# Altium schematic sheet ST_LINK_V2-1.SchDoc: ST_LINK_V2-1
size A3; Date: Not used; ApprovedBy: Not used; CheckedBy: Not used; Author: Not used; CompanyName: STMicroelectronics; DrawnBy: Not used; Engineer: Not used; Organization: Not used; Address1: Not used; Address2: Not used; Address3: Not used; Address4: Not used; DocumentNumber: 8; Revision: Not used; SheetNumber: 8; SheetTotal: 9
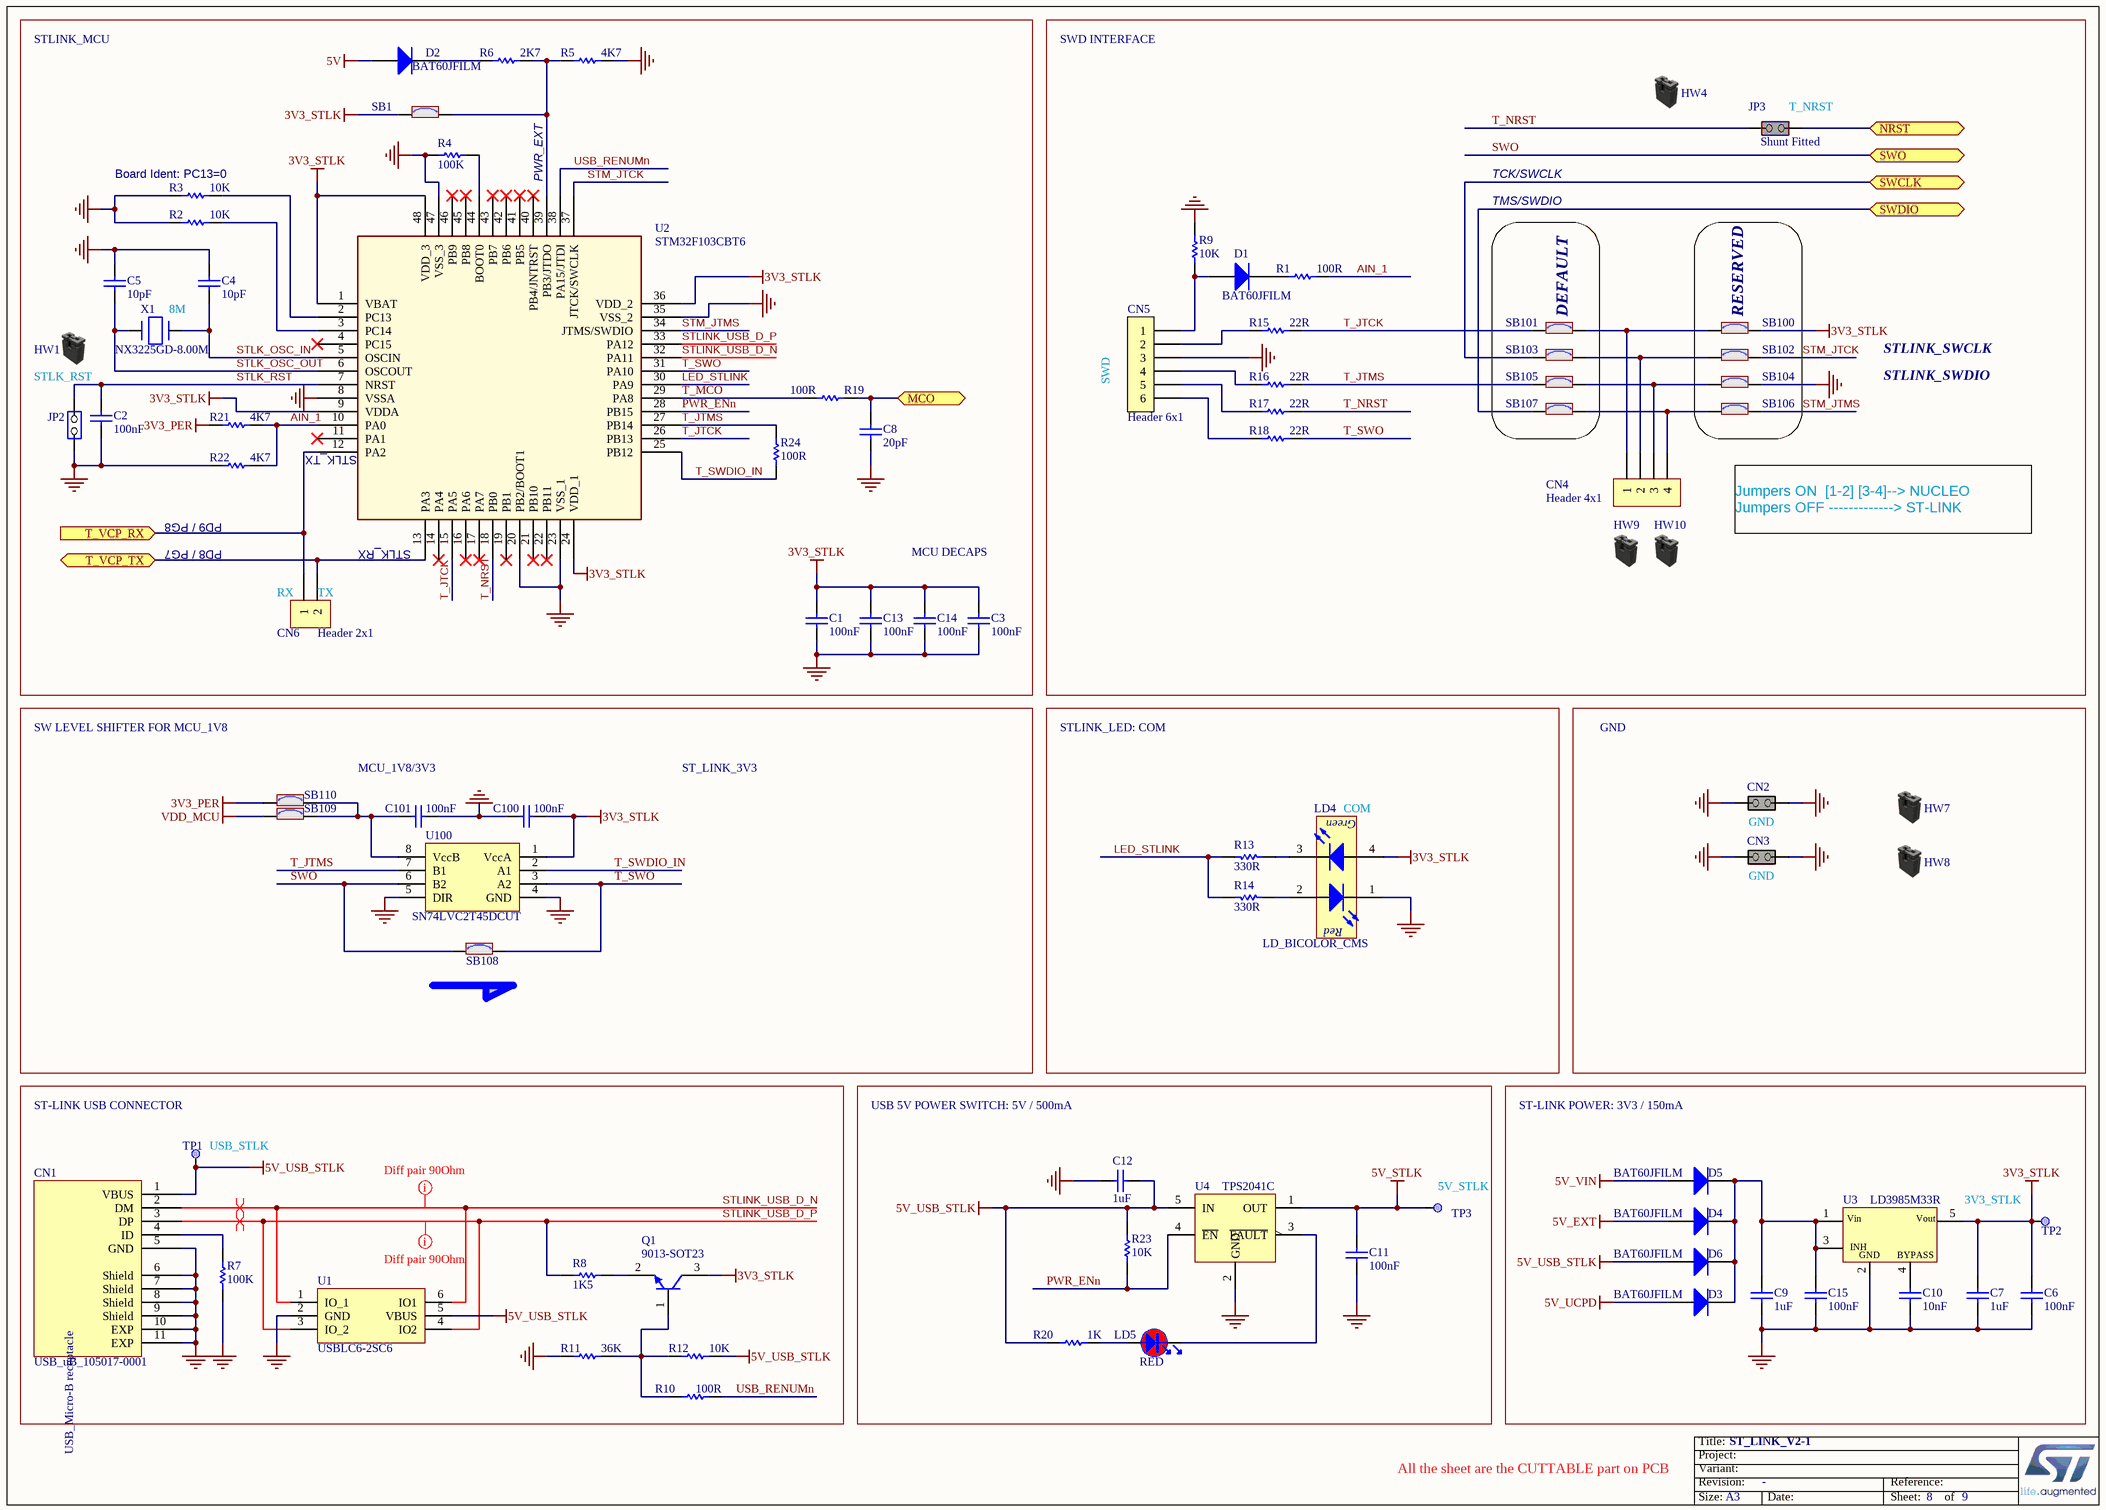
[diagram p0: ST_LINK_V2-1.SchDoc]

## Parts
C1  value 100nF  [C0603]
C2  value 100nF  [C0603]
C3  value 100nF  [C0603]
C4  value 10pF  [C0402]
C5  value 10pF  [C0402]
C6  value 100nF  [C0603]
C7  value 1uF  [C0603]  (hidden comment: Capacitor)
C8  value 20pF  [C0603]
C9  value 1uF  [C0603]
C10  value 10nF  [C0603]
C11  value 100nF  [C0603]
C12  value 1uF  [C0603]  (hidden comment: Capacitor)
C13  value 100nF  [C0603]
C14  value 100nF  [C0603]
C15  value 100nF  [C0603]
C100  value 100nF  [C0603]
C101  value 100nF  [C0603]
CN1  value USB_uB_105017-0001  [CON_USBMICROB_MOLEX_105017-0001_H2P90]
CN2  (no value)  [CON_SAMTEC_TSW-102-09-X-S]
CN3  (no value)  [CON_SAMTEC_TSW-102-09-X-S]
CN4  Header 4x1  [CON_SAMTEC_TSW-104-07-G-S]
CN5  value Header 6x1  [CON_SAMTEC_TSW-106-07-X-S]
CN6  value Header 2x1  [CON_SAMTEC_TSW-102-07-G-S]
D1  value BAT60JFILM  [DIO_SOD323]
D2  value BAT60JFILM  [DIO_SOD323]
D3  value BAT60JFILM  [DIO_SOD323]
D4  value BAT60JFILM  [DIO_SOD323]
D5  value BAT60JFILM  [DIO_SOD323]
D6  value BAT60JFILM  [DIO_SOD323]
HW1  (no value)  (mechanical)
HW4  (no value)  (mechanical)
HW7  (no value)  (mechanical)
HW8  (no value)  (mechanical)
HW9  (no value)  (mechanical)
HW10  (no value)  (mechanical)
JP2  (no value)  [CON_SAMTEC_TSW-102-07-G-S]
JP3  value Shunt Fitted  [CON_SAMTEC_TSW-102-07-G-S]
LD4  value LD_BICOLOR_CMS  [LED_BI-GR_HSMF-A201-A00J1]
LD5  value RED  [LED_0603_RED_H0P4]
Q1  value 9013-SOT23  [NPN_SOT23]
R1  value 100R  [R0603]
R2  value 10K  [R0603]
R3  value 10K  [R0603]
R4  value 100K  [R0603]
R5  value 4K7  [R0603]
R6  value 2K7  [R0603]
R7  value 100K  [R0603]
R8  value 1K5  [R0603]
R9  value 10K  [R0603]
R10  value 100R  [R0603]
R11  value 36K  [R0603]
R12  value 10K  [R0603]
R13  value 330R  [R0603]
R14  value 330R  [R0603]
R15  value 22R  [R0603]
R16  value 22R  [R0603]
R17  value 22R  [R0603]
R18  value 22R  [R0603]
R19  value 100R  [R0603]
R20  value 1K  [R0603]
R21  value 4K7  [R0603]
R22  value 4K7  [R0603]
R23  value 10K  [R0603]
R24  value 100R  [R0603]
SB1  (no value)  [SOLDER-BRIDGE_R0603-0R]
SB100  (no value)  [SOLDER-BRIDGE_R0603-0R]
SB101  (no value)  [SOLDER-BRIDGE_R0603-0R]
SB102  (no value)  [SOLDER-BRIDGE_R0603-0R]
SB103  (no value)  [SOLDER-BRIDGE_R0603-0R]
SB104  (no value)  [SOLDER-BRIDGE_R0603-0R]
SB105  (no value)  [SOLDER-BRIDGE_R0603-0R]
SB106  (no value)  [SOLDER-BRIDGE_R0603-0R]
SB107  (no value)  [SOLDER-BRIDGE_R0603-0R]
SB108  (no value)  [SOLDER-BRIDGE_R0603-0R]
SB109  (no value)  [SOLDER-BRIDGE_R0603-0R]
SB110  (no value)  [SOLDER-BRIDGE_R0603-0R]
TP1  (no value)  [TP_SMD_1MM]  (no BOM)
TP2  (no value)  [TP_SMD_1MM]  (no BOM)
TP3  (no value)  [TP_SMD_1MM]  (no BOM)
U1  value USBLC6-2SC6  [ESD_SOT23-6L]
U2  value STM32F103CBT6  [ICC_LQFP48_7X7_P050]
U3  value LD3985M33R  [REG_SOT23-5L]
U4  TPS2041C  [MOS_SOT23-5L]
U100  value SN74LVC2T45DCUT  [ICC_VSSOP8_DCU_R-PDSO-G8_2X2P30_P050]
X1  value NX3225GD-8.00M  [CRY_NX3225GD_2P]

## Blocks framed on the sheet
DEFAULT: SB101 SB103 SB105 SB107
RESERVED: SB100 SB102 SB104 SB106

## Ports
MCO, NRST, SWCLK, SWDIO, SWO, T_VCP_RX (in), T_VCP_TX

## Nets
3V3_PER: R21.1 SB110.2
3V3_STLK: C1.2 C3.2 C6.2 C7.2 C13.2 C14.2 C100.2 LD4.4(YellowGreen_anode) Q1.3(C) SB1.1 SB100.2 TP2.1 U2.1(VBAT) U2.9(VDDA) U2.24(VDD_1) U2.36(VDD_2) U2.48(VDD_3) U3.5(Vout) U100.1(VccA)
5V: D2.1(A)
5V_EXT: D4.1(A)
5V_STLK: C11.2 TP3.1 U4.1(OUT)
5V_UCPD: D3.1(A)
5V_USB_STLK: C12.2 CN1.1(VBUS) D6.1(A) R12.1 R20.1 R23.1 TP1.1 U1.5(VBUS) U4.5(IN)
5V_VIN: D5.1(A)
GND: C1.1 C2.1 C3.1 C4.2 C5.2 C6.1 C7.1 C8.2 C9.1 C10.1 C11.1 C12.1 C13.1 C14.1 C15.1 C100.1 C101.2 CN1.5(GND) CN1.6(Shield) CN1.7(Shield) CN1.8(Shield) CN1.9(Shield) CN1.10(EXP) CN1.11(EXP) CN2.1(COMMON) CN2.2(NO) CN3.1(COMMON) CN3.2(NO) CN5.3 JP2.1(COMMON) LD4.1(RED_cathode) R2.1 R3.1 R4.1 R5.2 R7.1 R9.2 R11.1 R22.1 SB104.2 U1.2(GND) U2.8(VSSA) U2.20(PB2/BOOT1) U2.23(VSS_1) U2.35(VSS_2) U2.47(VSS_3) U3.2(GND) U4.2(GND) U100.4(GND) U100.5(DIR)
VDD_MCU: SB109.2
AIN_1: R1.2 R21.2 R22.2 U2.10(PA0)
LED_STLINK: R13.2 R14.2 U2.30(PA9)
MCO: C8.1 R19.2 ; port MCO
NRST: JP3.2(NO) ; port NRST
PWR_ENn: R23.2 U2.28(PB15) U4.4(~{EN})
STLINK_USB_D_N: CN1.2(DM) U1.1(IO_1) U1.6(IO1) U2.32(PA11)
STLINK_USB_D_P: CN1.3(DP) R8.2 U1.3(IO_2) U1.4(IO2) U2.33(PA12)
STLK_OSC_IN: C4.1 U2.5(OSCIN) X1.1(X1)
STLK_OSC_OUT: C5.1 U2.6(OSCOUT) X1.2(X2)
STLK_RST: C2.2 JP2.2(NO) U2.7(NRST)
STM_JTCK: SB102.2 U2.37(JTCK/SWCLK)
STM_JTMS: SB106.2 U2.34(JTMS/SWDIO)
SWCLK: SB103.1 ; port SWCLK
SWDIO: SB107.1 ; port SWDIO
SWO: SB108.2 U100.6(B2) ; port SWO
T_JTCK: R15.2 SB101.1 U2.15(PA5) U2.26(PB13)
T_JTMS: R16.2 R24.2 SB105.1 U2.27(PB14) U100.7(B1)
T_MCO: R19.1 U2.29(PA8)
T_NRST: JP3.1(COMMON) R17.2 U2.18(PB0)
T_SWDIO_IN: R24.1 U2.25(PB12) U100.2(A1)
T_SWO: R18.2 SB108.1 U2.31(PA10) U100.3(A2)
T_VCP_RX: CN6.1 U2.12(PA2) ; port T_VCP_RX
T_VCP_TX: CN6.2 U2.13(PA3) ; port T_VCP_TX
USB_RENUMn: R10.2 U2.38(PA15/JTDI)
NetC9_2: C9.2 C15.2 D3.2(K) D4.2(K) D5.2(K) D6.2(K) U3.1(Vin) U3.3(CE)
NetC10_2: C10.2 U3.4(BYPASS)
NetC101_1: C101.1 SB109.1 SB110.1 U100.8(VccB)
NetCN1_4: CN1.4(ID) R7.2
NetCN4_1: CN4.1 SB100.1 SB101.2
NetCN4_2: CN4.2 SB102.1 SB103.2
NetCN4_3: CN4.3 SB104.1 SB105.2
NetCN4_4: CN4.4 SB106.1 SB107.2
NetCN5_1: CN5.1 D1.1(A) R9.1
NetCN5_2: CN5.2 R15.1
NetCN5_4: CN5.4 R16.1
NetCN5_5: CN5.5 R17.1
NetCN5_6: CN5.6 R18.1
NetD1_2: D1.2(K) R1.1
NetD2_2: D2.2(K) R6.1
NetLD4_2: LD4.2(Red_anode) R14.1
NetLD4_3: LD4.3(YellowGreen_cathode) R13.1
NetLD5_1: LD5.1 R20.2
NetLD5_2: LD5.2 U4.3(~{FAULT})
NetQ1_1: Q1.1(B) R10.1 R11.2 R12.2
NetQ1_2: Q1.2(E) R8.1
NetR2_2: R2.2 U2.3(PC14)
NetR3_2: R3.2 U2.2(PC13)
NetR4_2: R4.2 U2.44(BOOT0)
NetR5_1: R5.1 R6.2 SB1.2 U2.39(PB3/JTDO)

Not connected (* = marked no-connect by the designer): U2 4(PC15)* 11(PA1)* 14(PA4)* 16(PA6)* 17(PA7)* 19(PB1)* 21(PB10)* 22(PB11)* 40(PB4/JNTRST)* 41(PB5)* 42(PB6)* 43(PB7)* 45(PB8)* 46(PB9)*

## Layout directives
mark named Diff pair 90Ohm: STLINK_USB_D_N, STLINK_USB_D_P
differential pair: STLINK_USB_D_N, STLINK_USB_D_P

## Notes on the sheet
- STLINK_MCU
- SWD INTERFACE
- (near JP3) T_NRST
- (near R3) Board Ident: PC13=0
- PWR_EXT
- TCK/SWCLK
- TMS/SWDIO
- (near X1) 8M
- STLK_RST
- (near CN5) SWD
- STLINK_SWCLK
- STLINK_SWDIO
- (near U2) STLK_TX
- PD9 / PG8
- PD8 / PG7
- (near U2) STLK_RX
- MCU DECAPS
- Jumpers ON  [1-2] [3-4]--> NUCLEO
  Jumpers OFF -------------> ST-LINK
- (near CN6) RX
- (near CN6) TX
- SW LEVEL SHIFTER FOR MCU_1V8
- MCU_1V8/3V3
- ST_LINK_3V3
- STLINK_LED: COM
- GND
- (near LD4) COM
- (near CN2) GND
- (near CN3) GND
- ST-LINK USB CONNECTOR
- USB 5V POWER SWITCH: 5V / 500mA
- ST-LINK POWER: 3V3 / 150mA
- (near TP1) USB_STLK
- (near TP3) 5V_STLK
- 3V3_STLK
- All the sheet are the CUTTABLE part on PCB

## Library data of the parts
C1-C3 C6 C11 C13-C15 C100 C101 = MCD-00211: Capacitor, MLCC, 100nF, 16V, X7R, 10%, 0603, T=0,8mm; Manufacturer_Part_Number: CC0603KRX7R7BB104; Manufacturer: YAGEO; Provided_By: Subcon; Initial_Board_Reference: MB1319
C4 C5 = MCD-00015: Capacitor, MLCC, 10pF, 50V, NPO, 5%, 0402, T=0,5mm; Manufacturer_Part_Number: CC0402JRNPO9BN100; Manufacturer: YAGEO; Provided_By: subcon; Initial_Board_Reference: MB1274
C7 C12 = MCD-00010: Capacitor, MLCC, 1uF, 16V, X5R, 10%, 0603, T=0,8mm; Manufacturer_Part_Number: CC0603KRX5R7BB105; Manufacturer: YAGEO; Provided_By: SUBCO
C8 = MCD-00638: Capacitor, MLCC, 20pF, 50V, NPO, 5%, 0603, T=0,8mm; Manufacturer_Part_Number: CC0603JRNPO9BN200; Manufacturer: YAGEO; Provided_By: Subcon; Initial_Board_Reference: MB1319
C9 = MCD-00010: Capacitor, MLCC, 1uF, 16V, X5R, 10%, 0603, T=0,8mm; Manufacturer_Part_Number: CC0603KRX5R7BB105; Manufacturer: YAGEO; Provided_By: Subcon; Initial_Board_Reference: MB1274
C10 = MCD-00017: Capacitor, MLCC, 10nF, 50V, X7R, 10%, 0603, T=0.8mm; Manufacturer_Part_Number: CC0603KRX7R9BB103; Manufacturer: YAGEO; Provided_By: Subcon; Initial_Board_Reference: MB1274
CN1 = MCD-00028: USB-MICRO-B, 0.65mm, RA, SMT, Bottom Mount,; Manufacturer_Part_Number: 1050170001; Manufacturer: MOLEX; Part_Type: Connector; Provided_By: Subcon; Initial_Board_Reference: MB1274
CN2 CN3 = MCD-00214: Header, 2x1, 2,54mm, VR, TH, Height 5.84mm/10.16mm; Manufacturer_Part_Number: TSW-102-09-x-S; Manufacturer: SAMTEC; Part_Type: Connector; Value: Header 2x1 16mm; Provided_By: Subcon; Initial_Board_Reference: MB1319
CN4 = MCD-00029: Header, 4x1, 2,54mm, VR, TH, Height 5.84mm/2.54mm; Part_Type: Connector; Manufacturer_Part_Number: TSW-104-07-x-S; Manufacturer: SAMTEC; Provided_By: SUBCO; Initial_Board_Reference: MB1274; Path: ws/MCD_ApplicationBoards/Lists/MCDPARTSdatabase; Item Type: Item
CN5 = MCD-00212: Header, 6x1, 2,54mm, VR, TH, Height 5.84mm/2.54mm; Manufacturer_Part_Number: TSW-106-07-x-S; Manufacturer: SAMTEC; Part_Type: Connector; Provided_By: Subcon; Initial_Board_Reference: MB1319
CN6 = MCD-00032: Header, 2x1, 2,54mm, VR, TH, Height 5.84mm/2.54mm; Manufacturer_Part_Number: TSW-102-07-x-S; Manufacturer: SAMTEC; Part_Type: Connector; Provided_By: Subcon; Initial_Board_Reference: MB1274
D1-D6 = MCD-00034: BAT60JFILM; Manufacturer: STMICROELECTRONICS; Part_Type: Diode; ECCN_US: EAR99; ECCN_EU: NEC; Provided_By: Subcon; Initial_Board_Reference: MB1274
HW1 HW4 HW7-HW10 = MCD-00043: SHUNT 2.54mm BLACK; Manufacturer_Part_Number: SNT-100-BK-G; Manufacturer: SAMTEC; Part_Type: Mechanical; Provided_By: Subcon; Initial_Board_Reference: MB1274
JP2 = MCD-00045: Header, 2x1, 2,54mm, VR, TH, Height 5.84mm/2.54mm; Manufacturer_Part_Number: TSW-102-07-x-S; Manufacturer: SAMTEC; Part_Type: Connector; Value: Shunt not fitted; Provided_By: Subcon; Initial_Board_Reference: MB1274; Remark: 3D KO: BZ: 40098
JP3 = MCD-00683: Header, 2x1, 2,54mm, VR, TH, Height 5.84mm/2.54mm - Shunt Fitted by default; Part_Type: Connector; Manufacturer_Part_Number: TSW-102-07-x-S; Manufacturer: SAMTEC; Provided_By: Subcon; Initial_Board_Reference: MB1331
LD4 = MCD-00051: LED Bicolor; Manufacturer_Part_Number: HSMF-A201-A00J1; Manufacturer: AVAGO TECHNOLOGIES; Alternate_Manufacturer_Part_Number: LE-RGW35280; Alternate_Manufacturer: EVERLUCK; Part_Type: Display; ECCN_US: EAR99; ECCN_EU: NEC; Provided_By: Subcon; Initial_Board_Reference: MB1274
LD5 = MCD-00322: LED, Red, 0603; Part_Type: Display; Manufacturer_Part_Number: 19-217/R6C-AL1M2VY/3T; Manufacturer: EVERLIGHT; ECCN_US: EAR99; ECCN_EU: NEC; Provided_By: Subcon; Initial_Board_Reference: MB1311
Q1 = MCD-00073: NPN Bipolar Transistor; Manufacturer_Part_Number: BSR14; Manufacturer: NXP; Part_Type: IC; ECCN_US: EAR99; ECCN_EU: NEC; Provided_By: Subcon; Initial_Board_Reference: MB1274
R1 R10 R19 R24 = MCD-00224: Resistor,100R,0603,1%,1/10W; Manufacturer_Part_Number: RC0603FR-07100RL; Manufacturer: YAGEO; Provided_By: Subcon; Initial_Board_Reference: MB1319
R2 R3 R9 R12 R23 = MCD-00220: Resistor,10K,0603,1%,1/10W; Manufacturer_Part_Number: RC0603FR-0710KL; Manufacturer: YAGEO; Provided_By: Subcon; Initial_Board_Reference: MB1319
R4 R7 = MCD-00223: Resistor,100K,0603,1%,1/10W; Manufacturer_Part_Number: RC0603FR-07100KL; Manufacturer: YAGEO; Provided_By: Subcon; Initial_Board_Reference: MB1319
R5 R21 R22 = MCD-00219: Resistor,4K7,0603,1%,1/10W; Manufacturer_Part_Number: RC0603FR-074K7L; Manufacturer: YAGEO; Provided_By: Subcon; Initial_Board_Reference: MB1319
R6 = MCD-00218: Resistor,2K7,0603,1%,1/10W; Manufacturer_Part_Number: RC0603FR-072K7L; Manufacturer: YAGEO; Provided_By: Subcon; Initial_Board_Reference: MB1319
R8 = MCD-00217: Resistor,1K5,0603,1%,1/10W; Manufacturer_Part_Number: RC0603FR-071K5L; Manufacturer: YAGEO; Provided_By: Subcon; Initial_Board_Reference: MB1319
R11 = MCD-00221: Resistor,36K,0603,1%,1/10W; Manufacturer_Part_Number: RC0603FR-0736KL; Manufacturer: YAGEO; Provided_By: Subcon; Initial_Board_Reference: MB1319
R13 R14 = MCD-00197: Resistor,330R,0603,1%,1/10W; Manufacturer_Part_Number: RC0603FR-07330RL; Manufacturer: YAGEO; Provided_By: Subcon
R15-R18 = MCD-00190: Resistor,22R,0603,1%,1/10W; Manufacturer_Part_Number: RC0603FR-0722RL; Manufacturer: YAGEO; Provided_By: Subcon
R20 = MCD-00070: Resistor,1K,0603,1%,1/10W; Manufacturer_Part_Number: RC0603FR-071KL; Manufacturer: YAGEO; Provided_By: Subcon; Initial_Board_Reference: MB1274
SB1 SB100-SB110 = MCD-00071: Solder Bridge ON; Part_Type: Mechanical; Provided_By: Subcon; Initial_Board_Reference: MB1274
TP1-TP3 = MCD-00074: Test Point 1mm; Part_Type: Mechanical; Initial_Board_Reference: MB1274
U1 = MCD-00163: Very low capacitance ESD protection; Part_Type: IC; Manufacturer: STMICROELECTRONICS; ECCN_US: EAR99; ECCN_EU: NEC; Provided_By: Subcon; Initial_Board_Reference: MB1263
U2 = MCD-00085: Medium-density performance line ARM-based 32-bit MCU with 128KB Flash; Manufacturer: STMICROELECTRONICS; Part_Type: IC; ECCN_US: 3A991A2; ECCN_EU: NEC; Provided_By: Subcon; Initial_Board_Reference: MB1274
U3 = MCD-00086: Ultra low drop-low noise BiCMOS voltage, regulators low ESR capacitors compatible; Manufacturer: STMICROELECTRONICS; Part_Type: IC; ECCN_US: EAR99; ECCN_EU: NEC; Provided_By: Subcon; Initial_Board_Reference: MB1274
U4 = MCD-01785: 5V Power Switch, 0.85A, RDSon 130mOhm max, with active low enable pin; Part_Type: IC; Manufacturer_Part_Number: TPS2041CDBVT; Manufacturer: TEXAS INSTRUMENTS; ECCN_US: EAR99; ECCN_EU: NEC; Provided_By: SUBCO
U100 = MCD-00264: Dual bit dual supply bus transceiver; Part_Type: IC; Manufacturer: TEXAS INSTRUMENTS; ECCN_US: EAR99; ECCN_EU: NEC; Provided_By: Subcon; Initial_Board_Reference: MB1319
X1 = MCD-00092: Crystal 8Mhz, 8pF, -+50PPM, SMD; Manufacturer_Part_Number: NX3225GD 8MHz EXS00A-CG04874; Manufacturer: NDK; Part_Type: Crystal_Osc; ECCN_US: EAR99; ECCN_EU: NEC; Provided_By: STM; Initial_Board_Reference: MB1274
